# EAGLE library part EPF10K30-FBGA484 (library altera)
EPF10K30A FLEX 10K family
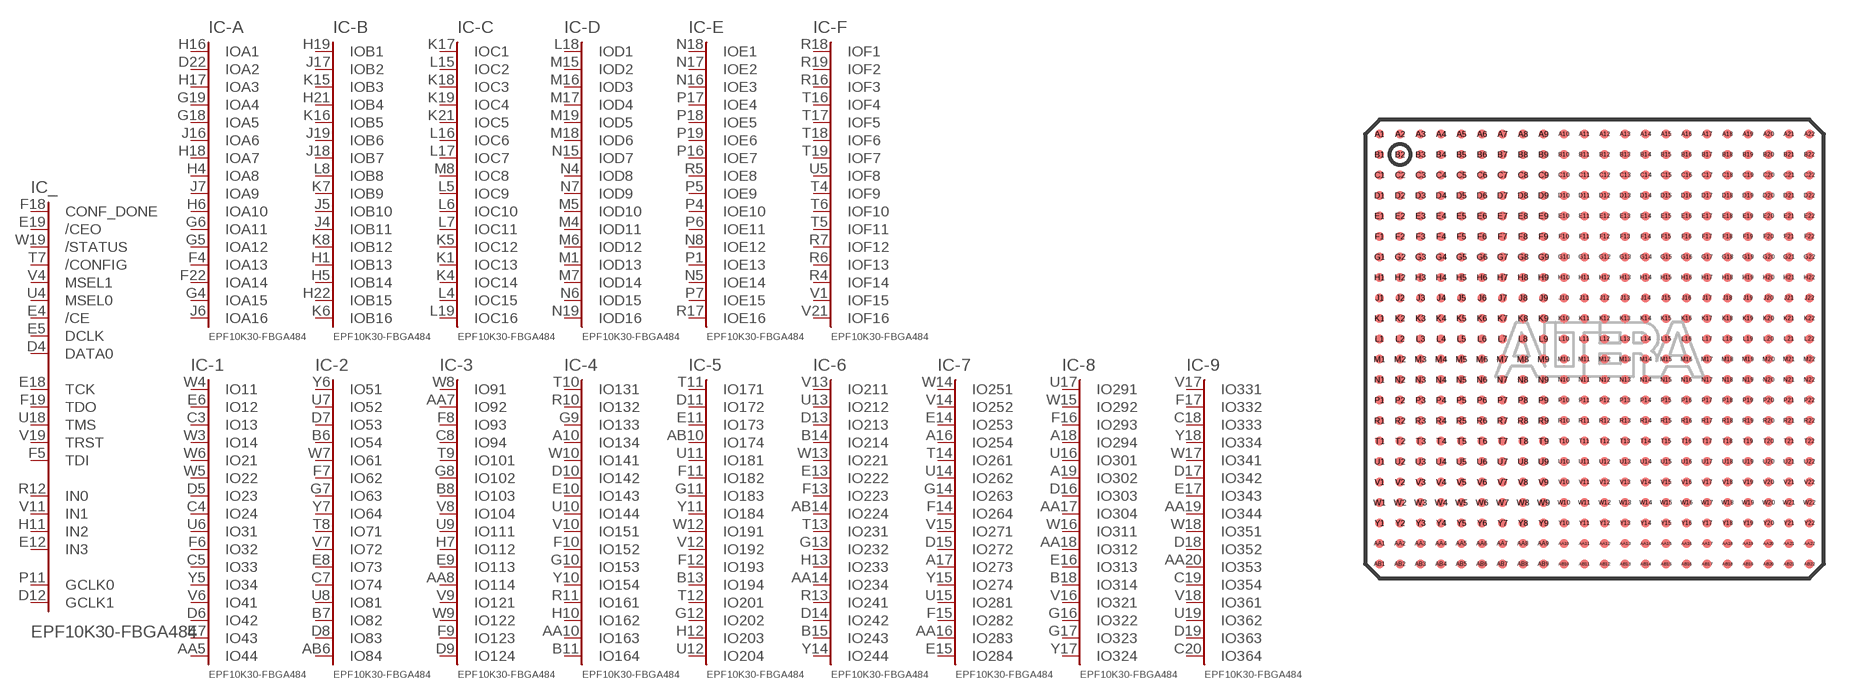
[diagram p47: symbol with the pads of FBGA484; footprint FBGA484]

Designator prefix IC; gates _=100R240C -A=A16 -B=B16 -C=C16 -D=D16 -E=E16 -F=F16 -1=IO44 -2=IO84 -3=IO124 -4=IO164 -5=IO204 -6=IO244 -7=IO284 -8=IO324 -9=IO364 G1=GND G2=GND G3=GND G4=GND G5=GND G6=GND G7=GND G8=GND G9=GND G10=GND G11=GND G12=GND G13=GND G14=GND G15=GND G16=GND G17=GND G18=GND G19=GND G20=GND G21=GND G22=GND G23=GND G24=GND G25=GND G26=GND G27=GND G28=GND G29=GND G30=GND G31=GND G32=GND G33=GND G34=GND G35=GND G36=GND G37=GND G38=GND G39=GND G40=GND G41=GND G42=GND G43=GND G44=GND G45=GND G46=GND G47=GND G48=GND G49=GND NC1=NC NC2=NC NC3=NC NC4=NC NC5=NC NC6=NC NC7=NC NC8=NC NC9=NC NC10=NC NC11=NC NC12=NC NC13=NC NC14=NC NC15=NC NC16=NC NC17=NC NC18=NC NC19=NC NC20=NC NC21=NC NC22=NC NC23=NC NC24=NC NC25=NC NC26=NC NC27=NC NC28=NC NC29=NC NC30=NC NC31=NC NC32=NC NC33=NC NC34=NC NC35=NC NC36=NC NC37=NC NC38=NC NC39=NC NC40=NC NC41=NC NC42=NC NC43=NC NC44=NC NC45=NC NC46=NC NC47=NC NC48=NC NC49=NC NC50=NC NC51=NC NC52=NC NC53=NC NC54=NC NC55=NC NC56=NC NC57=NC NC58=NC NC59=NC NC60=NC NC61=NC NC62=NC NC63=NC NC64=NC NC65=NC NC66=NC NC67=NC NC68=NC NC69=NC NC70=NC NC71=NC NC72=NC NC73=NC NC74=NC NC75=NC NC76=NC NC77=NC NC78=NC NC79=NC NC80=NC NC81=NC NC82=NC NC83=NC NC84=NC NC85=NC NC86=NC NC87=NC NC88=NC NC89=NC NC90=NC NC91=NC NC92=NC NC93=NC NC94=NC NC95=NC NC96=NC NC97=NC NC98=NC NC99=NC NC100=NC NC101=NC NC102=NC NC103=NC NC104=NC NC105=NC NC106=NC NC107=NC NC108=NC NC109=NC NC110=NC NC111=NC NC112=NC NC113=NC NC114=NC NC115=NC NC116=NC NC117=NC NC118=NC NC119=NC NC120=NC NC121=NC NC122=NC NC123=NC V1=VCCINT V2=VCCINT V3=VCCINT V4=VCCINT V5=VCCINT V6=VCCINT V7=VCCINT V8=VCCINT V9=VCCINT V10=VCCINT V11=VCCINT V12=VCCINT V13=VCCINT V14=VCCINT V15=VCCINT V16=VCCINT V17=VCCINT V18=VCCINT V19=VCCINT V20=VCCINT V21=VCCINT V22=VCCINT V23=VCCINT VO1=VCCIO VO2=VCCIO VO3=VCCIO VO4=VCCIO VO5=VCCIO VO6=VCCIO VO7=VCCIO VO8=VCCIO VO9=VCCIO VO10=VCCIO VO11=VCCIO VO12=VCCIO VO13=VCCIO VO14=VCCIO VO15=VCCIO VO16=VCCIO VO17=VCCIO VO18=VCCIO VO19=VCCIO VO20=VCCIO VO21=VCCIO VO22=VCCIO VO23=VCCIO VO24=VCCIO VO25=VCCIO VO26=VCCIO VO27=VCCIO VO28=VCCIO VO29=VCCIO

## EPF10K30-FBGA484 (MPN: EPF10K30AFC484-1; OC_FARNELL: unknown; OC_NEWARK: 51R8942)  [FBGA484]
A1  G6:GND  pwr
A2  NC25:NC  nc
A3  NC26:NC  nc
A4  NC27:NC  nc
A5  NC28:NC  nc
A6  VO2:VCCIO  pwr
A7  NC29:NC  nc
A8  G7:GND  pwr
A9  NC30:NC  nc
A10  -4:IO134
A11  NC31:NC  nc
A12  NC32:NC  nc
A13  VO3:VCCIO  pwr
A14  NC33:NC  nc
A15  NC34:NC  nc
A16  -7:IO254
A17  -7:IO273
A18  -8:IO294
A19  -8:IO302
A20  NC35:NC  nc
A21  NC36:NC  nc
A22  G8:GND  pwr
AA1  G1:GND  pwr
AA2  NC1:NC  nc
AA3  NC2:NC  nc
AA4  NC3:NC  nc
AA5  -1:IO44
AA6  G2:GND  pwr
AA7  -3:IO92
AA8  -3:IO114
AA9  NC4:NC  nc
AA10  -4:IO163
AA11  NC5:NC  nc
AA12  V1:VCC  pwr
AA13  NC6:NC  nc
AA14  -6:IO234
AA15  NC7:NC  nc
AA16  -7:IO283
AA17  -8:IO304
AA18  -8:IO312
AA19  -9:IO344
AA20  -9:IO353
AA21  NC8:NC  nc
AA22  G3:GND  pwr
AB1  NC9:NC  nc
AB2  NC10:NC  nc
AB3  NC11:NC  nc
AB4  NC12:NC  nc
AB5  NC13:NC  nc
AB6  -2:IO84
AB7  NC14:NC  nc
AB8  NC15:NC  nc
AB9  NC16:NC  nc
AB10  -5:IO174
AB11  G4:GND  pwr
AB12  NC17:NC  nc
AB13  VO1:VCCIO  pwr
AB14  -6:IO224
AB15  NC18:NC  nc
AB16  G5:GND  pwr
AB17  NC19:NC  nc
AB18  NC20:NC  nc
AB19  NC21:NC  nc
AB20  NC22:NC  nc
AB21  NC23:NC  nc
AB22  NC24:NC  nc
B1  G9:GND  pwr
B2  G10:GND  pwr
B3  NC37:NC  nc
B4  NC38:NC  nc
B5  VO4:VCCIO  pwr
B6  -2:IO54
B7  -2:IO82
B8  -3:IO103
B9  NC39:NC  nc
B10  NC40:NC  nc
B11  -4:IO164
B12  NC41:NC  nc
B13  -5:IO194
B14  -6:IO214
B15  -6:IO243
B16  NC42:NC  nc
B17  G11:GND  pwr
B18  -8:IO314
B19  NC43:NC  nc
B20  NC44:NC  nc
B21  G12:GND  pwr
B22  G13:GND  pwr
C1  NC45:NC  nc
C2  G14:GND  pwr
C3  -1:IO13
C4  -1:IO24
C5  -1:IO33
C6  NC46:NC  nc
C7  -2:IO74
C8  -3:IO94
C9  NC47:NC  nc
C10  NC48:NC  nc
C11  V2:VCC  pwr
C12  NC49:NC  nc
C13  NC50:NC  nc
C14  NC51:NC  nc
C15  V3:VCC  pwr
C16  NC52:NC  nc
C17  NC53:NC  nc
C18  -9:IO333
C19  -9:IO354
C20  -9:IO364
C21  G15:GND  pwr
C22  NC54:NC  nc
D1  NC55:NC  nc
D2  NC56:NC  nc
D3  NC57:NC  nc
D4  _:DATA0  in
D5  -1:IO23
D6  -1:IO42
D7  -2:IO53
D8  -2:IO83
D9  -3:IO124
D10  -4:IO142
D11  -5:IO172
D12  _:GCLK1  in
D13  -6:IO213
D14  -6:IO242
D15  -7:IO272
D16  -8:IO303
D17  -9:IO342
D18  -9:IO352
D19  -9:IO363
D20  NC58:NC  nc
D21  NC59:NC  nc
D22  -A:IOA2
E1  VO5:VCCIO  pwr
E2  NC60:NC  nc
E3  NC61:NC  nc
E4  _:/CE  in
E5  _:DCLK  in
E6  -1:IO12
E7  -1:IO43
E8  -2:IO73
E9  -3:IO113
E10  -4:IO143
E11  -5:IO173
E12  _:IN3  in
E13  -6:IO222
E14  -7:IO253
E15  -7:IO284
E16  -8:IO313
E17  -9:IO343
E18  _:TCK
E19  _:/CEO  in
E20  NC62:NC  nc
E21  G16:GND  pwr
E22  NC63:NC  nc
F1  NC64:NC  nc
F2  NC65:NC  nc
F3  NC66:NC  nc
F4  -A:IOA13
F5  _:TDI
F6  -1:IO32
F7  -2:IO62
F8  -3:IO93
F9  -3:IO123
F10  -4:IO152
F11  -5:IO182
F12  -5:IO193
F13  -6:IO223
F14  -7:IO264
F15  -7:IO282
F16  -8:IO293
F17  -9:IO332
F18  _:CONF_DONE  in
F19  _:TDO
F20  NC67:NC  nc
F21  NC68:NC  nc
F22  -A:IOA14
G1  VO6:VCCIO  pwr
G2  NC69:NC  nc
G3  G17:GND  pwr
G4  -A:IOA15
G5  -A:IOA12
G6  -A:IOA11
G7  -2:IO63
G8  -3:IO102
G9  -4:IO133
G10  -4:IO153
G11  -5:IO183
G12  -5:IO202
G13  -6:IO232
G14  -7:IO263
G15  VO7:VCCIO  pwr
G16  -8:IO322
G17  -8:IO323
G18  -A:IOA5
G19  -A:IOA4
G20  NC70:NC  nc
G21  G18:GND  pwr
G22  NC71:NC  nc
H1  -B:IOB13
H2  G19:GND  pwr
H3  NC72:NC  nc
H4  -A:IOA8
H5  -B:IOB14
H6  -A:IOA10
H7  -3:IO112
H8  G20:GND  pwr
H9  VO8:VCCIO  pwr
H10  -4:IO162
H11  _:IN2  in
H12  -5:IO203
H13  -6:IO233
H14  V4:VCC  pwr
H15  G21:GND  pwr
H16  -A:IOA1
H17  -A:IOA3
H18  -A:IOA7
H19  -B:IOB1
H20  VO9:VCCIO  pwr
H21  -B:IOB4
H22  -B:IOB15
J1  NC73:NC  nc
J2  NC74:NC  nc
J3  NC75:NC  nc
J4  -B:IOB11
J5  -B:IOB10
J6  -A:IOA16
J7  -A:IOA9
J8  V5:VCC  pwr
J9  G22:GND  pwr
J10  V6:VCC  pwr
J11  VO10:VCCIO  pwr
J12  V7:VCC  pwr
J13  VO11:VCCIO  pwr
J14  G23:GND  pwr
J15  V8:VCC  pwr
J16  -A:IOA6
J17  -B:IOB2
J18  -B:IOB7
J19  -B:IOB6
J20  G24:GND  pwr
J21  NC76:NC  nc
J22  NC77:NC  nc
K1  -C:IOC13
K2  NC78:NC  nc
K3  G25:GND  pwr
K4  -C:IOC14
K5  -C:IOC12
K6  -B:IOB16
K7  -B:IOB9
K8  -B:IOB12
K9  VO12:VCCIO  pwr
K10  G26:GND  pwr
K11  VO13:VCCIO  pwr
K12  G27:GND  pwr
K13  G28:GND  pwr
K14  VO14:VCCIO  pwr
K15  -B:IOB3
K16  -B:IOB5
K17  -C:IOC1
K18  -C:IOC3
K19  -C:IOC4
K20  VO15:VCCIO  pwr
K21  -C:IOC5
K22  NC79:NC  nc
L1  NC80:NC  nc
L2  NC81:NC  nc
L3  NC82:NC  nc
L4  -C:IOC15
L5  -C:IOC9
L6  -C:IOC10
L7  -C:IOC11
L8  -B:IOB8
L9  V9:VCC  pwr
L10  V10:VCC  pwr
L11  G29:GND  pwr
L12  G30:GND  pwr
L13  V11:VCC  pwr
L14  VO16:VCCIO  pwr
L15  -C:IOC2
L16  -C:IOC6
L17  -C:IOC7
L18  -D:IOD1
L19  -C:IOC16
L20  NC83:NC  nc
L21  NC84:NC  nc
L22  NC85:NC  nc
M1  -D:IOD13
M2  NC86:NC  nc
M3  NC87:NC  nc
M4  -D:IOD11
M5  -D:IOD10
M6  -D:IOD12
M7  -D:IOD14
M8  -C:IOC8
M9  VO17:VCCIO  pwr
M10  V12:VCC  pwr
M11  G31:GND  pwr
M12  G32:GND  pwr
M13  V13:VCC  pwr
M14  V14:VCC  pwr
M15  -D:IOD2
M16  -D:IOD3
M17  -D:IOD4
M18  -D:IOD6
M19  -D:IOD5
M20  G33:GND  pwr
M21  NC88:NC  nc
M22  NC89:NC  nc
N1  NC90:NC  nc
N2  NC91:NC  nc
N3  VO18:VCCIO  pwr
N4  -D:IOD8
N5  -E:IOE14
N6  -D:IOD15
N7  -D:IOD9
N8  -E:IOE12
N9  VO19:VCCIO  pwr
N10  G34:GND  pwr
N11  VO20:VCCIO  pwr
N12  V15:VCC  pwr
N13  G35:GND  pwr
N14  VO21:VCCIO  pwr
N15  -D:IOD7
N16  -E:IOE3
N17  -E:IOE2
N18  -E:IOE1
N19  -D:IOD16
N20  VO22:VCCIO  pwr
N21  NC92:NC  nc
N22  NC93:NC  nc
P1  -E:IOE13
P2  NC94:NC  nc
P3  NC95:NC  nc
P4  -E:IOE10
P5  -E:IOE9
P6  -E:IOE11
P7  -E:IOE15
P8  V16:VCC  pwr
P9  G36:GND  pwr
P10  V17:VCC  pwr
P11  _:GCLK0  in
P12  V18:VCC  pwr
P13  VO23:VCCIO  pwr
P14  G37:GND  pwr
P15  V19:VCC  pwr
P16  -E:IOE7
P17  -E:IOE4
P18  -E:IOE5
P19  -E:IOE6
P20  NC96:NC  nc
P21  NC97:NC  nc
P22  NC98:NC  nc
R1  VO24:VCCIO  pwr
R2  NC99:NC  nc
R3  NC100:NC  nc
R4  -F:IOF14
R5  -E:IOE8
R6  -F:IOF13
R7  -F:IOF12
R8  G38:GND  pwr
R9  VO25:VCCIO  pwr
R10  -4:IO132
R11  -4:IO161
R12  _:IN0  in
R13  -6:IO241
R14  V20:VCC  pwr
R15  G39:GND  pwr
R16  -F:IOF3
R17  -E:IOE16
R18  -F:IOF1
R19  -F:IOF2
R20  NC101:NC  nc
R21  NC102:NC  nc
R22  G40:GND  pwr
T1  G41:GND  pwr
T2  NC103:NC  nc
T3  VO26:VCCIO  pwr
T4  -F:IOF9
T5  -F:IOF11
T6  -F:IOF10
T7  _:/CONFIG  in
T8  -2:IO71
T9  -3:IO101
T10  -4:IO131
T11  -5:IO171
T12  -5:IO201
T13  -6:IO231
T14  -7:IO261
T15  VO27:VCCIO  pwr
T16  -F:IOF4
T17  -F:IOF5
T18  -F:IOF6
T19  -F:IOF7
T20  NC104:NC  nc
T21  NC105:NC  nc
T22  VO28:VCCIO  pwr
U1  NC106:NC  nc
U2  NC107:NC  nc
U3  NC108:NC  nc
U4  _:MSEL0  in
U5  -F:IOF8
U6  -1:IO31
U7  -2:IO52
U8  -2:IO81
U9  -3:IO111
U10  -4:IO144
U11  -5:IO181
U12  -5:IO204
U13  -6:IO212
U14  -7:IO262
U15  -7:IO281
U16  -8:IO301
U17  -8:IO291
U18  _:TMS
U19  -9:IO362
U20  NC109:NC  nc
U21  NC110:NC  nc
U22  NC111:NC  nc
V1  -F:IOF15
V2  NC112:NC  nc
V3  G42:GND  pwr
V4  _:MSEL1  in
V5  V21:VCC  pwr
V6  -1:IO41
V7  -2:IO72
V8  -3:IO104
V9  -3:IO121
V10  -4:IO151
V11  _:IN1  in
V12  -5:IO192
V13  -6:IO211
V14  -7:IO252
V15  -7:IO271
V16  -8:IO321
V17  -9:IO331
V18  -9:IO361
V19  _:TRST
V20  NC113:NC  nc
V21  -F:IOF16
V22  VO29:VCCIO  pwr
W1  NC114:NC  nc
W2  NC115:NC  nc
W3  -1:IO14
W4  -1:IO11
W5  -1:IO22
W6  -1:IO21
W7  -2:IO61
W8  -3:IO91
W9  -3:IO122
W10  -4:IO141
W11  G43:GND  pwr
W12  -5:IO191
W13  -6:IO221
W14  -7:IO251
W15  -8:IO292
W16  -8:IO311
W17  -9:IO341
W18  -9:IO351
W19  _:/STATUS  in
W20  G44:GND  pwr
W21  V22:VCC  pwr
W22  NC116:NC  nc
Y1  G45:GND  pwr
Y2  G46:GND  pwr
Y3  G47:GND  pwr
Y4  NC117:NC  nc
Y5  -1:IO34
Y6  -2:IO51
Y7  -2:IO64
Y8  V23:VCC  pwr
Y9  NC118:NC  nc
Y10  -4:IO154
Y11  -5:IO184
Y12  NC119:NC  nc
Y13  NC120:NC  nc
Y14  -6:IO244
Y15  -7:IO274
Y16  NC121:NC  nc
Y17  -8:IO324
Y18  -9:IO334
Y19  NC122:NC  nc
Y20  NC123:NC  nc
Y21  G48:GND  pwr
Y22  G49:GND  pwr

## Footprint FBGA484 (pad centres in mm)
Fine Ball Grid Array
smd 0.45 x 0.45: A1 -10.5,10.5; A2 -9.5,10.5; A3 -8.5,10.5; A4 -7.5,10.5; A5 -6.5,10.5; A6 -5.5,10.5; A7 -4.5,10.5; A8 -3.5,10.5; A9 -2.5,10.5; A10 -1.5,10.5; A11 -0.5,10.5; A12 0.5,10.5; A13 1.5,10.5; A14 2.5,10.5; A15 3.5,10.5; A16 4.5,10.5; A17 5.5,10.5; A18 6.5,10.5; A19 7.5,10.5; A20 8.5,10.5; A21 9.5,10.5; A22 10.5,10.5; AA1 -10.5,-9.5; AA2 -9.5,-9.5; AA3 -8.5,-9.5; AA4 -7.5,-9.5; AA5 -6.5,-9.5; AA6 -5.5,-9.5; AA7 -4.5,-9.5; AA8 -3.5,-9.5; AA9 -2.5,-9.5; AA10 -1.5,-9.5; AA11 -0.5,-9.5; AA12 0.5,-9.5; AA13 1.5,-9.5; AA14 2.5,-9.5; AA15 3.5,-9.5; AA16 4.5,-9.5; AA17 5.5,-9.5; AA18 6.5,-9.5; AA19 7.5,-9.5; AA20 8.5,-9.5; AA21 9.5,-9.5; AA22 10.5,-9.5; AB1 -10.5,-10.5; AB2 -9.5,-10.5; AB3 -8.5,-10.5; AB4 -7.5,-10.5; AB5 -6.5,-10.5; AB6 -5.5,-10.5; AB7 -4.5,-10.5; AB8 -3.5,-10.5; AB9 -2.5,-10.5; AB10 -1.5,-10.5; AB11 -0.5,-10.5; AB12 0.5,-10.5; AB13 1.5,-10.5; AB14 2.5,-10.5; AB15 3.5,-10.5; AB16 4.5,-10.5; AB17 5.5,-10.5; AB18 6.5,-10.5; AB19 7.5,-10.5; AB20 8.5,-10.5; AB21 9.5,-10.5; AB22 10.5,-10.5; B1 -10.5,9.5; B2 -9.5,9.5; B3 -8.5,9.5; B4 -7.5,9.5; B5 -6.5,9.5; B6 -5.5,9.5; B7 -4.5,9.5; B8 -3.5,9.5; B9 -2.5,9.5; B10 -1.5,9.5; B11 -0.5,9.5; B12 0.5,9.5; B13 1.5,9.5; B14 2.5,9.5; B15 3.5,9.5; B16 4.5,9.5; B17 5.5,9.5; B18 6.5,9.5; B19 7.5,9.5; B20 8.5,9.5; B21 9.5,9.5; B22 10.5,9.5; C1 -10.5,8.5; C2 -9.5,8.5; C3 -8.5,8.5; C4 -7.5,8.5; C5 -6.5,8.5; C6 -5.5,8.5; C7 -4.5,8.5; C8 -3.5,8.5; C9 -2.5,8.5; C10 -1.5,8.5; C11 -0.5,8.5; C12 0.5,8.5; C13 1.5,8.5; C14 2.5,8.5; C15 3.5,8.5; C16 4.5,8.5; C17 5.5,8.5; C18 6.5,8.5; C19 7.5,8.5; C20 8.5,8.5; C21 9.5,8.5; C22 10.5,8.5; D1 -10.5,7.5; D2 -9.5,7.5; D3 -8.5,7.5; D4 -7.5,7.5; D5 -6.5,7.5; D6 -5.5,7.5; D7 -4.5,7.5; D8 -3.5,7.5; D9 -2.5,7.5; D10 -1.5,7.5; D11 -0.5,7.5; D12 0.5,7.5; D13 1.5,7.5; D14 2.5,7.5; D15 3.5,7.5; D16 4.5,7.5; D17 5.5,7.5; D18 6.5,7.5; D19 7.5,7.5; D20 8.5,7.5; D21 9.5,7.5; D22 10.5,7.5; E1 -10.5,6.5; E2 -9.5,6.5; E3 -8.5,6.5; E4 -7.5,6.5; E5 -6.5,6.5; E6 -5.5,6.5; E7 -4.5,6.5; E8 -3.5,6.5; E9 -2.5,6.5; E10 -1.5,6.5; E11 -0.5,6.5; E12 0.5,6.5; E13 1.5,6.5; E14 2.5,6.5; E15 3.5,6.5; E16 4.5,6.5; E17 5.5,6.5; E18 6.5,6.5; E19 7.5,6.5; E20 8.5,6.5; E21 9.5,6.5; E22 10.5,6.5; F1 -10.5,5.5; F2 -9.5,5.5; F3 -8.5,5.5; F4 -7.5,5.5; F5 -6.5,5.5; F6 -5.5,5.5; F7 -4.5,5.5; F8 -3.5,5.5; F9 -2.5,5.5; F10 -1.5,5.5; F11 -0.5,5.5; F12 0.5,5.5; F13 1.5,5.5; F14 2.5,5.5; F15 3.5,5.5; F16 4.5,5.5; F17 5.5,5.5; F18 6.5,5.5; F19 7.5,5.5; F20 8.5,5.5; F21 9.5,5.5; F22 10.5,5.5; G1 -10.5,4.5; G2 -9.5,4.5; G3 -8.5,4.5; G4 -7.5,4.5; G5 -6.5,4.5; G6 -5.5,4.5; G7 -4.5,4.5; G8 -3.5,4.5; G9 -2.5,4.5; G10 -1.5,4.5; G11 -0.5,4.5; G12 0.5,4.5; G13 1.5,4.5; G14 2.5,4.5; G15 3.5,4.5; G16 4.5,4.5; G17 5.5,4.5; G18 6.5,4.5; G19 7.5,4.5; G20 8.5,4.5; G21 9.5,4.5; G22 10.5,4.5; H1 -10.5,3.5; H2 -9.5,3.5; H3 -8.5,3.5; H4 -7.5,3.5; H5 -6.5,3.5; H6 -5.5,3.5; H7 -4.5,3.5; H8 -3.5,3.5; H9 -2.5,3.5; H10 -1.5,3.5; H11 -0.5,3.5; H12 0.5,3.5; H13 1.5,3.5; H14 2.5,3.5; H15 3.5,3.5; H16 4.5,3.5; H17 5.5,3.5; H18 6.5,3.5; H19 7.5,3.5; H20 8.5,3.5; H21 9.5,3.5; H22 10.5,3.5; J1 -10.5,2.5; J2 -9.5,2.5; J3 -8.5,2.5; J4 -7.5,2.5; J5 -6.5,2.5; J6 -5.5,2.5; J7 -4.5,2.5; J8 -3.5,2.5; J9 -2.5,2.5; J10 -1.5,2.5; J11 -0.5,2.5; J12 0.5,2.5; J13 1.5,2.5; J14 2.5,2.5; J15 3.5,2.5; J16 4.5,2.5; J17 5.5,2.5; J18 6.5,2.5; J19 7.5,2.5; J20 8.5,2.5; J21 9.5,2.5; J22 10.5,2.5; K1 -10.5,1.5; K2 -9.5,1.5; K3 -8.5,1.5; K4 -7.5,1.5; K5 -6.5,1.5; K6 -5.5,1.5; K7 -4.5,1.5; K8 -3.5,1.5; K9 -2.5,1.5; K10 -1.5,1.5; K11 -0.5,1.5; K12 0.5,1.5; K13 1.5,1.5; K14 2.5,1.5; K15 3.5,1.5; K16 4.5,1.5; K17 5.5,1.5; K18 6.5,1.5; K19 7.5,1.5; K20 8.5,1.5; K21 9.5,1.5; K22 10.5,1.5; L1 -10.5,0.5; L2 -9.5,0.5; L3 -8.5,0.5; L4 -7.5,0.5; L5 -6.5,0.5; L6 -5.5,0.5; L7 -4.5,0.5; L8 -3.5,0.5; L9 -2.5,0.5; L10 -1.5,0.5; L11 -0.5,0.5; L12 0.5,0.5; L13 1.5,0.5; L14 2.5,0.5; L15 3.5,0.5; L16 4.5,0.5; L17 5.5,0.5; L18 6.5,0.5; L19 7.5,0.5; L20 8.5,0.5; L21 9.5,0.5; L22 10.5,0.5; M1 -10.5,-0.5; M2 -9.5,-0.5; M3 -8.5,-0.5; M4 -7.5,-0.5; M5 -6.5,-0.5; M6 -5.5,-0.5; M7 -4.5,-0.5; M8 -3.5,-0.5; M9 -2.5,-0.5; M10 -1.5,-0.5; M11 -0.5,-0.5; M12 0.5,-0.5; M13 1.5,-0.5; M14 2.5,-0.5; M15 3.5,-0.5; M16 4.5,-0.5; M17 5.5,-0.5; M18 6.5,-0.5; M19 7.5,-0.5; M20 8.5,-0.5; M21 9.5,-0.5; M22 10.5,-0.5; N1 -10.5,-1.5; N2 -9.5,-1.5; N3 -8.5,-1.5; N4 -7.5,-1.5; N5 -6.5,-1.5; N6 -5.5,-1.5; N7 -4.5,-1.5; N8 -3.5,-1.5; N9 -2.5,-1.5; N10 -1.5,-1.5; N11 -0.5,-1.5; N12 0.5,-1.5; N13 1.5,-1.5; N14 2.5,-1.5; N15 3.5,-1.5; N16 4.5,-1.5; N17 5.5,-1.5; N18 6.5,-1.5; N19 7.5,-1.5; N20 8.5,-1.5; N21 9.5,-1.5; N22 10.5,-1.5; P1 -10.5,-2.5; P2 -9.5,-2.5; P3 -8.5,-2.5; P4 -7.5,-2.5; P5 -6.5,-2.5; P6 -5.5,-2.5; P7 -4.5,-2.5; P8 -3.5,-2.5; P9 -2.5,-2.5; P10 -1.5,-2.5; P11 -0.5,-2.5; P12 0.5,-2.5; P13 1.5,-2.5; P14 2.5,-2.5; P15 3.5,-2.5; P16 4.5,-2.5; P17 5.5,-2.5; P18 6.5,-2.5; P19 7.5,-2.5; P20 8.5,-2.5; P21 9.5,-2.5; P22 10.5,-2.5; R1 -10.5,-3.5; R2 -9.5,-3.5; R3 -8.5,-3.5; R4 -7.5,-3.5; R5 -6.5,-3.5; R6 -5.5,-3.5; R7 -4.5,-3.5; R8 -3.5,-3.5; R9 -2.5,-3.5; R10 -1.5,-3.5; R11 -0.5,-3.5; R12 0.5,-3.5; R13 1.5,-3.5; R14 2.5,-3.5; R15 3.5,-3.5; R16 4.5,-3.5; R17 5.5,-3.5; R18 6.5,-3.5; R19 7.5,-3.5; R20 8.5,-3.5; R21 9.5,-3.5; R22 10.5,-3.5; T1 -10.5,-4.5; T2 -9.5,-4.5; T3 -8.5,-4.5; T4 -7.5,-4.5; T5 -6.5,-4.5; T6 -5.5,-4.5; T7 -4.5,-4.5; T8 -3.5,-4.5; T9 -2.5,-4.5; T10 -1.5,-4.5; T11 -0.5,-4.5; T12 0.5,-4.5; T13 1.5,-4.5; T14 2.5,-4.5; T15 3.5,-4.5; T16 4.5,-4.5; T17 5.5,-4.5; T18 6.5,-4.5; T19 7.5,-4.5; T20 8.5,-4.5; T21 9.5,-4.5; T22 10.5,-4.5; U1 -10.5,-5.5; U2 -9.5,-5.5; U3 -8.5,-5.5; U4 -7.5,-5.5; U5 -6.5,-5.5; U6 -5.5,-5.5; U7 -4.5,-5.5; U8 -3.5,-5.5; U9 -2.5,-5.5; U10 -1.5,-5.5; U11 -0.5,-5.5; U12 0.5,-5.5; U13 1.5,-5.5; U14 2.5,-5.5; U15 3.5,-5.5; U16 4.5,-5.5; U17 5.5,-5.5; U18 6.5,-5.5; U19 7.5,-5.5; U20 8.5,-5.5; U21 9.5,-5.5; U22 10.5,-5.5; V1 -10.5,-6.5; V2 -9.5,-6.5; V3 -8.5,-6.5; V4 -7.5,-6.5; V5 -6.5,-6.5; V6 -5.5,-6.5; V7 -4.5,-6.5; V8 -3.5,-6.5; V9 -2.5,-6.5; V10 -1.5,-6.5; V11 -0.5,-6.5; V12 0.5,-6.5; V13 1.5,-6.5; V14 2.5,-6.5; V15 3.5,-6.5; V16 4.5,-6.5; V17 5.5,-6.5; V18 6.5,-6.5; V19 7.5,-6.5; V20 8.5,-6.5; V21 9.5,-6.5; V22 10.5,-6.5; W1 -10.5,-7.5; W2 -9.5,-7.5; W3 -8.5,-7.5; W4 -7.5,-7.5; W5 -6.5,-7.5; W6 -5.5,-7.5; W7 -4.5,-7.5; W8 -3.5,-7.5; W9 -2.5,-7.5; W10 -1.5,-7.5; W11 -0.5,-7.5; W12 0.5,-7.5; W13 1.5,-7.5; W14 2.5,-7.5; W15 3.5,-7.5; W16 4.5,-7.5; W17 5.5,-7.5; W18 6.5,-7.5; W19 7.5,-7.5; W20 8.5,-7.5; W21 9.5,-7.5; W22 10.5,-7.5; Y1 -10.5,-8.5; Y2 -9.5,-8.5; Y3 -8.5,-8.5; Y4 -7.5,-8.5; Y5 -6.5,-8.5; Y6 -5.5,-8.5; Y7 -4.5,-8.5; Y8 -3.5,-8.5; Y9 -2.5,-8.5; Y10 -1.5,-8.5; Y11 -0.5,-8.5; Y12 0.5,-8.5; Y13 1.5,-8.5; Y14 2.5,-8.5; Y15 3.5,-8.5; Y16 4.5,-8.5; Y17 5.5,-8.5; Y18 6.5,-8.5; Y19 7.5,-8.5; Y20 8.5,-8.5; Y21 9.5,-8.5; Y22 10.5,-8.5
